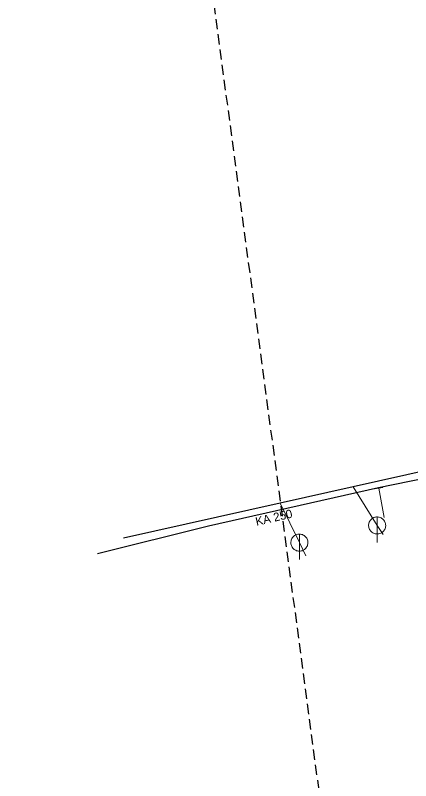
# Model space of a CAD drawing. Extents: x -682839 to -682312, y -994645 to -993949.
# Drawn here: x -682751.4 to -682705.1, y -994308.3 to -994218.6 of the extents above; entities that cross this region are included whole.
import ezdxf

# ---------------------------------------------------------------- set-up
doc = ezdxf.new("R2010")
doc.units = 0
doc.header["$LTSCALE"] = 0.4
doc.linetypes.add('MEDIUM_DASHED', pattern=[4.5, 3, -1.5])
doc.layers.add('1', color=7, linetype='Continuous')
for name, color, linetype, lineweight in [('11', 7, 'Continuous', 13), ('13', 7, 'Continuous', 13), ('14', 7, 'Continuous', 25), ('17', 7, 'Continuous', 25), ('22', 7, 'Continuous', 13), ('34', 7, 'Continuous', 13), ('63', 7, 'MEDIUM_DASHED', 25)]:
    doc.layers.add(name, color=color, linetype=linetype, lineweight=lineweight)

msp = doc.modelspace()

# ---------------------------------------------------------------- linework, layer by layer
at = {"layer": '11'}
for p, q in [((-682709.016, -994278.39), (-682711.829, -994273.859)), ((-682718.124, -994280.401), (-682720.37, -994275.78)), ((-682708.322, -994279.454), (-682709.016, -994278.39)), ((-682717.37, -994281.952), (-682718.124, -994280.401))]:
    msp.add_line(p, q, dxfattribs=at)
at = {"layer": '13'}
msp.add_line((-682708.83, -994274.019), (-682708.18, -994277.469), dxfattribs=at)
at = {"layer": '14', "lineweight": 13}
msp.add_line((-682708.84, -994273.969), (-682708.83, -994274.019), dxfattribs=at)
at = {"layer": '14'}
msp.add_lwpolyline([(-682702.57, -994271.78), (-682711.829, -994273.859), (-682720.37, -994275.78), (-682738.739, -994279.899)], dxfattribs=at)
at = {"layer": '17'}
msp.add_lwpolyline([(-682667.88, -994266.789), (-682668.739, -994267.21), (-682669.02, -994265.78), (-682680.579, -994268.21), (-682682.859, -994268.649), (-682708.84, -994273.969), (-682728.789, -994278.48), (-682741.8, -994281.719)], dxfattribs=at)
at = {"layer": '22'}
for p, q in [((-682709.016, -994280.39), (-682709.015, -994277.39)), ((-682718.124, -994282.401), (-682718.123, -994279.401))]:
    msp.add_line(p, q, dxfattribs=at)
for points in [[(-682708.016, -994278.39), (-682708.021, -994278.281), (-682708.039, -994278.173), (-682708.069, -994278.067), (-682708.109, -994277.966), (-682708.161, -994277.869), (-682708.223, -994277.779), (-682708.295, -994277.696), (-682708.375, -994277.622), (-682708.463, -994277.556), (-682708.557, -994277.501), (-682708.657, -994277.456), (-682708.762, -994277.423), (-682708.869, -994277.401), (-682708.978, -994277.391), (-682709.088, -994277.393), (-682709.196, -994277.407), (-682709.303, -994277.432), (-682709.406, -994277.469), (-682709.504, -994277.518), (-682709.596, -994277.576), (-682709.682, -994277.645), (-682709.759, -994277.722), (-682709.828, -994277.808), (-682709.887, -994277.9), (-682709.935, -994277.998), (-682709.972, -994278.101), (-682709.998, -994278.208), (-682710.012, -994278.316), (-682710.015, -994278.426), (-682710.005, -994278.535), (-682709.984, -994278.642), (-682709.95, -994278.746), (-682709.906, -994278.846), (-682709.851, -994278.941), (-682709.785, -994279.029), (-682709.711, -994279.109), (-682709.628, -994279.181), (-682709.538, -994279.243), (-682709.442, -994279.295), (-682709.34, -994279.336), (-682709.235, -994279.366), (-682709.127, -994279.384), (-682709.017, -994279.39), (-682708.908, -994279.384), (-682708.8, -994279.366), (-682708.695, -994279.337), (-682708.593, -994279.296), (-682708.496, -994279.244), (-682708.406, -994279.182), (-682708.323, -994279.111), (-682708.248, -994279.031), (-682708.183, -994278.943), (-682708.127, -994278.849), (-682708.083, -994278.749), (-682708.049, -994278.645), (-682708.027, -994278.537), (-682708.017, -994278.428)], [(-682717.124, -994280.401), (-682717.129, -994280.292), (-682717.147, -994280.184), (-682717.177, -994280.078), (-682717.217, -994279.977), (-682717.269, -994279.88), (-682717.331, -994279.79), (-682717.403, -994279.707), (-682717.483, -994279.633), (-682717.571, -994279.567), (-682717.665, -994279.512), (-682717.765, -994279.467), (-682717.87, -994279.434), (-682717.977, -994279.412), (-682718.086, -994279.402), (-682718.196, -994279.404), (-682718.304, -994279.418), (-682718.411, -994279.443), (-682718.514, -994279.48), (-682718.612, -994279.529), (-682718.704, -994279.587), (-682718.79, -994279.656), (-682718.867, -994279.733), (-682718.936, -994279.819), (-682718.995, -994279.911), (-682719.043, -994280.009), (-682719.08, -994280.112), (-682719.106, -994280.219), (-682719.12, -994280.327), (-682719.123, -994280.437), (-682719.113, -994280.546), (-682719.092, -994280.653), (-682719.058, -994280.757), (-682719.014, -994280.857), (-682718.959, -994280.952), (-682718.893, -994281.04), (-682718.819, -994281.12), (-682718.736, -994281.192), (-682718.646, -994281.254), (-682718.55, -994281.306), (-682718.448, -994281.347), (-682718.343, -994281.377), (-682718.235, -994281.395), (-682718.125, -994281.401), (-682718.016, -994281.395), (-682717.908, -994281.377), (-682717.803, -994281.348), (-682717.701, -994281.307), (-682717.604, -994281.255), (-682717.514, -994281.193), (-682717.431, -994281.122), (-682717.356, -994281.042), (-682717.291, -994280.954), (-682717.235, -994280.86), (-682717.191, -994280.76), (-682717.157, -994280.656), (-682717.135, -994280.548), (-682717.125, -994280.439)]]:
    msp.add_lwpolyline(points, close=True, dxfattribs=at)
at = {"layer": '34'}
msp.add_line((-682708.338, -994273.925), (-682709.321, -994274.111), dxfattribs=at)
at = {"layer": '63'}
msp.add_lwpolyline([(-682494.62, -994477.955), (-682564.4, -994570.065), (-682564.4, -994570.065), (-682684.423, -994544.944), (-682684.423, -994544.944), (-682751.412, -994042.525), (-682751.412, -994042.525), (-682670.466, -994042.525), (-682670.466, -994042.525)], close=True, dxfattribs=at)

# ---------------------------------------------------------------- texts
at = {"layer": '1'}
msp.add_text('KA 250', height=1, rotation=13, dxfattribs=at).set_placement((-682723.145, -994278.437))

doc.saveas('drawing.dxf')
